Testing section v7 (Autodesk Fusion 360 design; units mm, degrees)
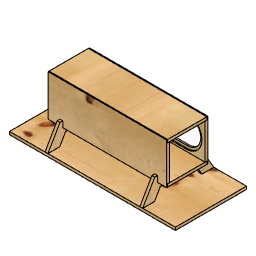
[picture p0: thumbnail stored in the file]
sketch "Front" plane through (0, 0, 0) normal (0, 0, 1) x axis (1, 0, 0)
  line L1 (500, 0) -> (0, 0)
  line L2 (500, 174) -> (500, 0)
  line L3 (0, 174) -> (500, 174)
  line L4 (0, 0) -> (0, 174)
  line L5 (500, 87) -> (0, 87)
  line L6 (420, 30) -> (80, 30)
  line L7 (80, 144) -> (420, 144)
  line L8 (420, 87) -> (80, 87)
  arc A1 centre (420, 87) radius 57 clockwise from (420, 144) to (420, 30)
  arc A2 centre (80, 87) radius 57 clockwise from (80, 30) to (80, 144)
  point P1 (0, 0)
  point P2 (0, 0)
  point P6 (0, 87)
  point P7 (500, 87)
  point P13 (420, 87)
  point P3 (500, 0)
  point P5 (0, 174)
  point P12 (80, 87)
  horizontal L1
  vertical L2
  horizontal L3
  vertical L4
  coincident P1 P2
  midpoint L4 P6
  midpoint L2 P7
  tangent L6 A1
  tangent A1 L7
  parallel L6 L7
  tangent L7 A2
  tangent L6 A2
  coincident L5 P13
  parallel L5 L8
  dimension "d1" distance P2 P3 = 500
  dimension "d2" distance P2 P5 = 174
  dimension "d3" distance P6 P12 = 80
  dimension "d4" distance L2 P13 = 80
  dimension "d5" distance L3 L7 = 30
  dimension "d6" radius A2 = 57
  dimension "d7" distance P12 P13 = 340
extrude "Extrude1" new body sketch "Front" profile of L1 L2 L3 L4 L6 A1 L7 A2 along normal blind 12 bodies "Front"
sketch "front noching" plane through (0, 0, 12) normal (0, 0, 1) x axis (1, 0, 0)
  line L1 (420, 144) -> (80, 144)
  line L2 (80, 30) -> (420, 30)
  line L3 (0, 0) -> (0, 174)
  line L4 (500, 0) -> (0, 0)
  line L5 (500, 174) -> (500, 0)
  line L6 (0, 174) -> (500, 174)
  line L7 (500, 174) -> (0, 174)
  line L8 (500, 162) -> (500, 174)
  line L9 (0, 162) -> (500, 162)
  line L10 (0, 174) -> (0, 162)
  line L11 (500, 87) -> (0, 87)
  line L12 (500, 0) -> (0, 0)
  line L13 (500, 12) -> (500, 0)
  line L14 (0, 12) -> (500, 12)
  line L15 (0, 0) -> (0, 12)
  line L16 (420.1, 20) -> (79.9, 20)
  line L17 (79.9, 154) -> (420.1, 154)
  line L18 (420.1, 87) -> (79.9, 87)
  arc A1 centre (80, 87) radius 57 clockwise from (80, 30) to (80, 144)
  arc A2 centre (420, 87) radius 57 clockwise from (420, 144) to (420, 30)
  arc A3 centre (420.1, 87) radius 67 clockwise from (420.1, 154) to (420.1, 20)
  arc A4 centre (79.9, 87) radius 67 clockwise from (79.9, 20) to (79.9, 154)
  point P14 (500, 162)
  point P8 (0, 174)
  point P12 (0, 174)
  point P16 (0, 87)
  point P17 (500, 87)
  point P20 (500, 12)
  point P1 (0, 0)
  point P18 (0, 0)
  point P27 (420.1, 87)
  point P4 (80, 87)
  point P26 (79.9, 87)
  point P7 (420, 87)
  horizontal L7
  vertical L8
  horizontal L9
  vertical L10
  coincident L5 P14
  coincident P8 P12
  midpoint L3 P16
  midpoint L5 P17
  horizontal L12
  vertical L13
  horizontal L14
  vertical L15
  coincident L5 P20
  coincident P1 P18
  tangent L16 A3
  tangent A3 L17
  parallel L16 L17
  tangent L17 A4
  tangent L16 A4
  coincident L11 P27
  parallel L11 L18
  dimension "d10" distance L12 L14 = 12
  dimension "d11" distance L7 L9 = 12
  dimension "d12" distance P4 P26 = 0.1
  dimension "d13" distance P7 P27 = 0.1
  dimension "d14" distance L1 L17 = 10
  dimension "d15" distance L2 L16 = 10
extrude "Extrude2" cut sketch "front noching" profile of L3 L4 L5 L6 L7 L8 L9 L10 L12 L13 L14 L15 against normal blind 8
extrude "Extrude3" cut sketch "front noching" profile of A1 L1 A2 L2 L16 A3 L17 A4 against normal blind 5
sketch "Top" plane through (0, 174, 0) normal (0, 1, 0) x axis (-1, 0, 0)
  line L1 (-500, 4) -> (0, 4)
  line L2 (-500, 0) -> (-500, 4)
  line L3 (0, 0) -> (-500, 0)
  line L4 (0, 4) -> (0, 0)
  line L5 (-500, 4) -> (0, 4)
  line L6 (-500, 170) -> (-500, 4)
  line L7 (0, 170) -> (-500, 170)
  line L8 (0, 4) -> (0, 170)
  point P2 (0, 4)
  point P6 (0, 4)
  point P7 (-500, 4)
  point P8 (-500, 170)
  point P9 (0, 170)
  horizontal L5
  vertical L6
  horizontal L7
  vertical L8
  coincident P2 P6
  dimension "d20" distance P7 P8 = 166 (= "150 mm + 16 mm")
  dimension "d21" distance P8 P9 = 500
extrude "Extrude4" new body sketch "Top" profile of L1 L5 L6 L7 L8 against normal blind 12 bodies "Top"
sketch "Bottom" plane through (0, 0, 0) normal (-1, 0, 0) x axis (0, 0, 1)
  line L1 (4, 162) -> (12, 162)
  line L2 (4, 174) -> (4, 162)
  line L3 (0, 174) -> (4, 174)
  line L4 (0, 0) -> (0, 174)
  line L5 (4, 0) -> (0, 0)
  line L6 (4, 12) -> (4, 0)
  line L7 (12, 12) -> (4, 12)
  line L8 (12, 162) -> (12, 12)
  line L9 (170, 0) -> (4, 0)
  line L10 (170, 12) -> (170, 0)
  line L11 (4, 12) -> (170, 12)
  line L12 (4, 0) -> (4, 12)
  point P7 (4, 0)
  point P10 (4, 0)
  point P11 (170, 0)
  horizontal L9
  vertical L10
  horizontal L11
  vertical L12
  coincident P7 P10
  dimension "d24" distance P10 P11 = 166
  dimension "d25" distance L9 L11 = 12
extrude "Extrude5" new body sketch "Bottom" profile of L6 L7 L9 L10 L11 L12 against normal blind 500 bodies "Bottom"
sketch "Back" plane through (0, 0, 0) normal (-1, 0, 0) x axis (0, 0, 1)
  line L1 (4, 174) -> (170, 174)
  line L2 (4, 162) -> (4, 174)
  line L3 (170, 162) -> (4, 162)
  line L4 (170, 174) -> (170, 162)
  line L5 (174, 174) -> (170, 174)
  line L6 (174, 0) -> (174, 174)
  line L7 (170, 0) -> (174, 0)
  line L8 (162, 162) -> (170, 162)
  line L9 (162, 12) -> (162, 162)
  line L10 (170, 12) -> (162, 12)
  line L11 (170, 162) -> (170, 12)
  line L12 (170, 12) -> (170, 0)
  line L13 (170, 174) -> (170, 162)
  point P2 (170, 174)
  point P6 (170, 174)
  point P5 (170, 162)
  point P10 (170, 162)
  point P11 (162, 162)
  point P12 (162, 12)
  horizontal L5
  vertical L6
  horizontal L7
  vertical L12
  coincident P2 P6
  horizontal L8
  vertical L9
  horizontal L10
  vertical L11
  coincident P5 P10
  collinear L12 L13
  dimension "d28" distance L6 L12 = 4
  dimension "d29" distance L6 L9 = 12
  dimension "d30" distance L5 L7 = 174
  dimension "d31" distance P11 P12 = 150
extrude "Extrude6" new body sketch "Back" profile of L3 L4 L5 L6 L7 L13 L8 L9 L10 L11 against normal blind 500 bodies "Back"
sketch "Window" plane through (0, 0, 12) normal (0, 0, 1) x axis (1, 0, 0)
  line L1 (79.9, 20) -> (420.1, 20)
  line L2 (420.1, 154) -> (79.9, 154)
  line L3 (0, 162) -> (500, 162)
  line L4 (0, 12) -> (0, 162)
  line L5 (500, 12) -> (0, 12)
  line L6 (500, 162) -> (500, 12)
  line L7 (487.1, 87) -> (12.9, 87)
  line L8 (79.9, 154) -> (420.1, 154)
  line L9 (420.1, 20) -> (79.9, 20)
  line L10 (12.9, 87) -> (487.1, 87)
  arc A1 centre (79.9, 87) radius 67 clockwise from (79.9, 20) to (79.9, 154)
  arc A2 centre (420.1, 87) radius 67 clockwise from (420.1, 154) to (420.1, 20)
  arc A3 centre (79.9, 87) radius 67 clockwise from (79.9, 20) to (79.9, 154)
  arc A4 centre (420.1, 87) radius 67 clockwise from (420.1, 154) to (420.1, 20)
  point P12 (12.9, 87)
  point P13 (487.1, 87)
  midpoint A1 P12
  midpoint A2 P13
  tangent L8 A3
  tangent A3 L9
  parallel L8 L9
  tangent L9 A4
  tangent L8 A4
  midpoint P13 A4
  midpoint P12 A3
extrude "Extrude7" new body sketch "Window" profile of L1 A1 L2 A2 L8 A3 L9 A4 against normal blind 5 bodies "window"
sketch "Stand Legs" plane through (0, 0, 0) normal (1, 0, 0) x axis (0, 0, -1)
  line L1 (-174, 174) -> (0, 174)
  line L2 (-174, 0) -> (-174, 174)
  line L3 (0, 0) -> (-174, 0)
  line L4 (0, 174) -> (0, 0)
  line L5 (-174, 0) -> (0, 174)
  line L6 (0, 0) -> (-174, 174)
  line L7 (63, 237) -> (-237, 237)
  line L8 (63, -63) -> (63, 237)
  line L9 (-237, -63) -> (63, -63)
  line L10 (-237, 237) -> (-237, -63)
  line L11 (63, -63) -> (-237, 237)
  line L12 (-237, -63) -> (63, 237)
  line L13 (-87, 0) -> (-87, 174)
  line L14 (12, 25.3346) -> (0, 25.3346)
  line L15 (63, -63) -> (12, 25.3346)
  line L16 (13, -63) -> (63, -63)
  line L17 (-11.8261, -20) -> (13, -63)
  line L18 (-87, -64.937) -> (-87, 0)
  line L19 (0, 0) -> (0, 25.3346)
  line L20 (0, 0) -> (-87, 0)
  line L21 (-87, -18.4309) -> (-87, 0)
  line L22 (-87, -20) -> (-11.8261, -20)
  line L23 (-87, -18.4309) -> (-87, 0)
  line L24 (-174, 0) -> (-87, 0)
  line L25 (-186, 25.3346) -> (-174, 25.3346)
  line L26 (-237, -63) -> (-186, 25.3346)
  line L27 (-162.1739, -20) -> (-187, -63)
  line L28 (-87, -20) -> (-162.1739, -20)
  line L29 (-187, -63) -> (-237, -63)
  line L30 (-174, 0) -> (-174, 25.3346)
  line L31 (20.5, -75) -> (20.5, -63)
  line L32 (55.5, -75) -> (20.5, -75)
  line L33 (55.5, -63) -> (55.5, -75)
  line L34 (-194.5, -75) -> (-194.5, -63)
  line L35 (-229.5, -75) -> (-194.5, -75)
  line L36 (-229.5, -63) -> (-229.5, -75)
  point P1 (0, 0)
  point P5 (0, 0)
  point P4 (-174, 0)
  point P6 (-174, 0)
  point P2 (0, 174)
  point P7 (0, 174)
  point P8 (0, 174)
  point P9 (-174, 0)
  point P10 (0, 0)
  point P15 (-87, 87)
  point P16 (-87, 174)
  point P17 (-87, 0)
  point P18 (0, 25.3346)
  point P20 (13, -63)
  point P23 (0, 0)
  point P24 (0, 0)
  point P25 (-87, -18.4309)
  point P13 (63, -63)
  point P32 (-237, -63)
  point P27 (-87, 0)
  point P30 (-174, 25.3346)
  point P19 (12, 25.3346)
  point P31 (-186, 25.3346)
  point P33 (-187, -63)
  point P21 (-11.8261, -20)
  point P34 (-162.1739, -20)
  point P36 (-174, 0)
  point P29 (-174, 0)
  point P28 (-87, -18.4309)
  point P26 (-87, -20)
  point P35 (-87, -20)
  point P37 (55.5, -63)
  point P44 (-229.5, -63)
  point P38 (20.5, -63)
  point P41 (-194.5, -63)
  point P39 (20.5, -75)
  point P42 (-194.5, -75)
  point P40 (55.5, -75)
  point P43 (-229.5, -75)
  point P11 (-237, 237)
  point P12 (63, 237)
  horizontal L1
  vertical L2
  horizontal L3
  vertical L4
  coincident P1 P5
  coincident P4 P6
  coincident P2 P7
  coincident P7 P8
  coincident P6 P9
  coincident P1 P10
  horizontal L7
  perpendicular L7 L8
  parallel L7 L9
  parallel L8 L10
  coincident L11 P15
  coincident L12 P15
  midpoint L6 P15
  midpoint L1 P16
  midpoint L3 P17
  coincident L4 P18
  perpendicular L4 L14
  coincident L9 P20
  perpendicular L3 L18
  coincident P1 P23
  coincident P1 P24
  coincident L18 P25
  perpendicular L18 L22
  parallel L15 L17
  symmetric P13 L18 P32
  symmetric P17 L18 P27
  symmetric P18 L18 P30
  symmetric P19 L18 P31
  symmetric P20 L18 P33
  symmetric P21 L18 P34
  symmetric L18 P23 P36
  symmetric L18 P24 P29
  symmetric L18 P25 P28
  symmetric L18 P26 P35
  vertical L31
  horizontal L32
  vertical L33
  coincident L16 P37
  symmetric L18 P37 P44
  symmetric L18 P38 P41
  symmetric L18 P39 P42
  symmetric L18 P40 P43
  dimension "d36" distance P11 P12 = 300
  dimension "d37" distance P12 P13 = 300
  dimension "d38" distance P18 P19 = 12
  dimension "d39" angle L15 L16 = 60
  dimension "d40" distance L3 L22 = 20
  dimension "d41" distance P20 P21 = 43
  dimension "d42" angle L17 L22 = 120
  dimension "d43" distance P13 P20 = 50
  dimension "d46" distance P37 P40 = 12
  dimension "d47" distance P39 P40 = 35
  dimension "d48" distance P13 L33 = 7.5
extrude "Extrude8" new body sketch "Stand Legs" profile of L14 L15 L16 L17 L19 L20 L22 L24 L25 L26 L27 L28 L29 L30 along normal blind 12 bodies "Stand legs1"
move "Move1"
copy_paste_bodies "CopyPasteBodies1"
move "Move2"
sketch "finger joint" plane through (50, 0, 0) normal (-1, 0, 0) x axis (0, 0, 1)
  line L1 (186, 25.3346) -> (237, -63)
  line L2 (174, 25.3346) -> (186, 25.3346)
  line L3 (174, 0) -> (174, 25.3346)
  line L4 (0, 0) -> (174, 0)
  line L5 (0, 25.3346) -> (0, 0)
  line L6 (-12, 25.3346) -> (0, 25.3346)
  line L7 (-63, -63) -> (-12, 25.3346)
  line L8 (-13, -63) -> (-63, -63)
  line L9 (11.8261, -20) -> (-13, -63)
  line L10 (162.1739, -20) -> (11.8261, -20)
  line L11 (187, -63) -> (162.1739, -20)
  line L12 (237, -63) -> (187, -63)
  line L13 (-20.5, -63) -> (-55.5, -63)
  line L14 (-20.5, -75) -> (-20.5, -63)
  line L15 (-55.5, -75) -> (-20.5, -75)
  line L16 (-55.5, -63) -> (-55.5, -75)
  line L17 (87, -88.8512) -> (87, -20)
  line L18 (194.5, -63) -> (229.5, -63)
  line L19 (194.5, -75) -> (194.5, -63)
  line L20 (229.5, -63) -> (229.5, -75)
  line L21 (229.5, -75) -> (194.5, -75)
  point P14 (-55.5, -63)
  point P18 (87, -20)
  point P20 (229.5, -63)
  point P15 (-20.5, -63)
  point P21 (194.5, -63)
  point P16 (-20.5, -75)
  point P22 (194.5, -75)
  point P17 (-55.5, -75)
  point P23 (229.5, -75)
  point P9 (-63, -63)
  horizontal L13
  vertical L14
  horizontal L15
  vertical L16
  coincident L8 P14
  midpoint L10 P18
  perpendicular L10 L17
  symmetric P14 L17 P20
  symmetric P15 L17 P21
  symmetric P16 L17 P22
  symmetric P17 L17 P23
  dimension "d49" distance P9 P14 = 7.5
  dimension "d50" distance P16 P17 = 35
  dimension "d51" distance P15 P16 = 12
extrude "Extrude9" add sketch "finger joint" profile of L8 L12 L13 L14 L15 L16 L18 L19 L20 L21 against normal blind 12
sketch "finger joint (1)" plane through (462, 0, 0) normal (1, 0, 0) x axis (0, 0, -1)
  line L1 (-237, -63) -> (-186, 25.3346)
  line L2 (-187, -63) -> (-237, -63)
  line L3 (-162.1739, -20) -> (-187, -63)
  line L4 (-11.8261, -20) -> (-162.1739, -20)
  line L5 (13, -63) -> (-11.8261, -20)
  line L6 (63, -63) -> (13, -63)
  line L7 (12, 25.3346) -> (63, -63)
  line L8 (0, 25.3346) -> (12, 25.3346)
  line L9 (0, 0) -> (0, 25.3346)
  line L10 (-174, 0) -> (0, 0)
  line L11 (-174, 25.3346) -> (-174, 0)
  line L12 (-186, 25.3346) -> (-174, 25.3346)
  line L13 (-194.5, -63) -> (-229.5, -63)
  line L14 (-194.5, -75) -> (-194.5, -63)
  line L15 (-229.5, -75) -> (-194.5, -75)
  line L16 (-229.5, -63) -> (-229.5, -75)
  line L17 (-87, -73.3472) -> (-87, -20)
  line L18 (20.5, -63) -> (55.5, -63)
  line L19 (55.5, -63) -> (55.5, -75)
  line L20 (20.5, -75) -> (20.5, -63)
  line L21 (55.5, -75) -> (20.5, -75)
  point P14 (-229.5, -63)
  point P18 (-87, -20)
  point P20 (55.5, -63)
  point P15 (-194.5, -63)
  point P21 (20.5, -63)
  point P16 (-194.5, -75)
  point P23 (20.5, -75)
  point P17 (-229.5, -75)
  point P22 (55.5, -75)
  point P3 (-237, -63)
  horizontal L13
  vertical L14
  horizontal L15
  vertical L16
  coincident L2 P14
  midpoint L4 P18
  perpendicular L4 L17
  symmetric P14 L17 P20
  symmetric P15 L17 P21
  symmetric P16 L17 P23
  symmetric P17 L17 P22
  dimension "d54" distance P14 P17 = 12
  dimension "d55" distance P16 P17 = 35
  dimension "d56" distance P3 P14 = 7.5
extrude "Extrude10" add sketch "finger joint (1)" profile of L2 L6 L13 L14 L15 L16 L18 L19 L20 L21 against normal blind 12
work_plane "WorkPlane1" AlongDistance 75
sketch "Sketch10" plane through (0, -75, 0) normal (0, -1, 0) x axis (-1, 0, 0)
  line L1 (-600, -237) -> (100, -237)
  line L2 (-600, 63) -> (-600, -237)
  line L3 (100, 63) -> (-600, 63)
  line L4 (100, -237) -> (100, 63)
  line L5 (-462, -229.5) -> (-462, -194.5)
  line L6 (-450, -229.5) -> (-462, -229.5)
  line L7 (-450, -194.5) -> (-450, -229.5)
  line L8 (-462, -194.5) -> (-450, -194.5)
  line L9 (-462, 20.5) -> (-462, 55.5)
  line L10 (-450, 20.5) -> (-462, 20.5)
  line L11 (-450, 55.5) -> (-450, 20.5)
  line L12 (-462, 55.5) -> (-450, 55.5)
  line L13 (-50, 55.5) -> (-50, 20.5)
  line L14 (-62, 55.5) -> (-50, 55.5)
  line L15 (-62, 20.5) -> (-62, 55.5)
  line L16 (-50, 20.5) -> (-62, 20.5)
  line L17 (-50, -194.5) -> (-50, -229.5)
  line L18 (-62, -194.5) -> (-50, -194.5)
  line L19 (-62, -229.5) -> (-62, -194.5)
  line L20 (-50, -229.5) -> (-62, -229.5)
  point P6 (-62, 63)
  point P2 (100, -237)
  point P3 (-600, -237)
  point P5 (100, 63)
  horizontal L1
  vertical L2
  horizontal L3
  vertical L4
  coincident L3 P6
  dimension "d60" distance P2 P3 = 700
  dimension "d62" distance P2 P5 = 300
extrude "Extrude11" new body sketch "Sketch10" against normal blind 12 bodies "platform"
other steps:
base_feature "Base Feature" bodies "Stand legs2"
named bodies: "Front", "Top", "Bottom", "Back", "window", "Stand legs1", "Stand legs2", "platform"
